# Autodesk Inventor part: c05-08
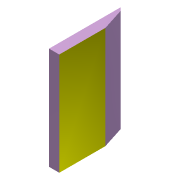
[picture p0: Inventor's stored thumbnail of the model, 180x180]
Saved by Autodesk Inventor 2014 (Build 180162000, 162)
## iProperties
Created: 2010-11
Part Number: c05-08
Material: Generic
Document SubType Name: Modeling
Designer: Thom Tremblay
Density: 1 g/cm^3
Appearance: Satin - Lavender
Author: Thom Tremblay
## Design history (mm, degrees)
sketch "Sketch1"
  geometry: L1 (0, 0)-(10, 0); L2 (10, 0)-(10, 70); L3 (10, 70)-(0, 70); L4 (0, 70)-(0, 0); L5 (3, 67)-(10, 45); L6 (0, 70)-(3, 67); 1 further point
  constraints: 12 end point, 2 parallel, 2 point on line, 1 horizontal, 1 perpendicular
  dimensions: "d0" = 10 distance of L3.end L2.end; "d1" = 70 distance of L2.end L1.end; "d3" = 25 vertical distance of point (2.045, 70) L5.end; "d6" = 45 deg angle of L4 L6; "d7" = 3 distance from line of L4 L5.start
extrude "Extrusion1" new body sketch "Sketch1" stored distance "d4" = 100; taper "d5" = 0 deg
body "Solid1"
